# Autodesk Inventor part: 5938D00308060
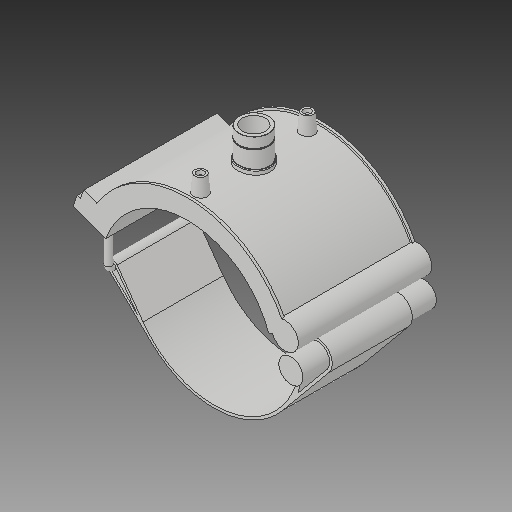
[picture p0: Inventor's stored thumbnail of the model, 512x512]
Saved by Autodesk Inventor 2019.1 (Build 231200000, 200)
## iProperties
Created: 2017-07
Part Number: 5938D00308060
Material: Generic
Description: PLASSON TRANSITION SADDLE 8''DIPS x 1"NPT
Document SubType Name: Modeling
Designer: KIM
Density: 1 g/cm^3
Appearance: Default
Author: KIM
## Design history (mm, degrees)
derived "5938D.ipt"
feature "Solid1::5938D.ipt"
tag "TaggingFeature1"
body "Solid1"
other parameters: "d0" = 228.9, "d1" = 274.68, "d2" = 449.58, "d3" = 57.225, "d4" = 176.022, "d5" = 0, "d40" = 142.8336, "d41" = 42.4074, "d43" = 0, "d45" = 0, "d47" = 179.25, "d48" = 39.3783, "d50" = 0, "d78" = 159.34, "d79" = 15, "d80" = 70.4088, "d82" = 5 deg, "d84" = 4, "d85" = 14, "d86" = 0, "d87" = 3, "d88" = 0, "d96" = 280.1736, "d97" = 3.52044, "d98" = 0, "d102" = 0.90873, "d103" = 30.291, "d104" = 25.146, "d105" = 0, "d106" = 24.2328, "d108" = 0, "d109" = -13.97, "d111" = 0.5, "d112" = 0.5, "d113" = 0, "d114" = 0.5, "d117" = 0.30291, "d120" = 140 deg, "d121" = 24.228, "d122" = 20 deg, "d123" = 1098.72, "d124" = 164.808, "d126" = 0, "d143" = 235.767, "d145" = 35.21538, "d149" = 3.4335, "d150" = 38.73692, "d153" = 176.022, "d154" = 0, "d156" = 137.34, "d157" = 160 deg, "d159" = 9.156, "d161" = 3.4335, "d162" = 105.6132, "d163" = 0, "d164" = 114.45, "d167" = 22.89, "d168" = 133.99024, "d170" = 3.4335, "d172" = 0, "d173" = 1, "d175" = 114.45, "d176" = 20 deg, "d177" = 16.023, "d178" = 45.78, "d180" = 0, "d183" = 18.312, "d184" = 12.8184, "d185" = 57.20715, "d186" = 57.20715, "d187" = 137.34, "d188" = 13.734, "d189" = 16.023, "d190" = 0, "d191" = 164.808, "d193" = 9.156, "d194" = 4.69245, "d195" = 90 deg, "d197" = 0, "d199" = 0, "d_" = 228.9, "B_" = 179.832, "H_" = 41.91, "L_" = 176.022, "d_t" = 6, "G_" = 30.291, "d148" = 3.4335, "d160" = 3.4335, "d169" = 3.4335, "d192" = 9.156
